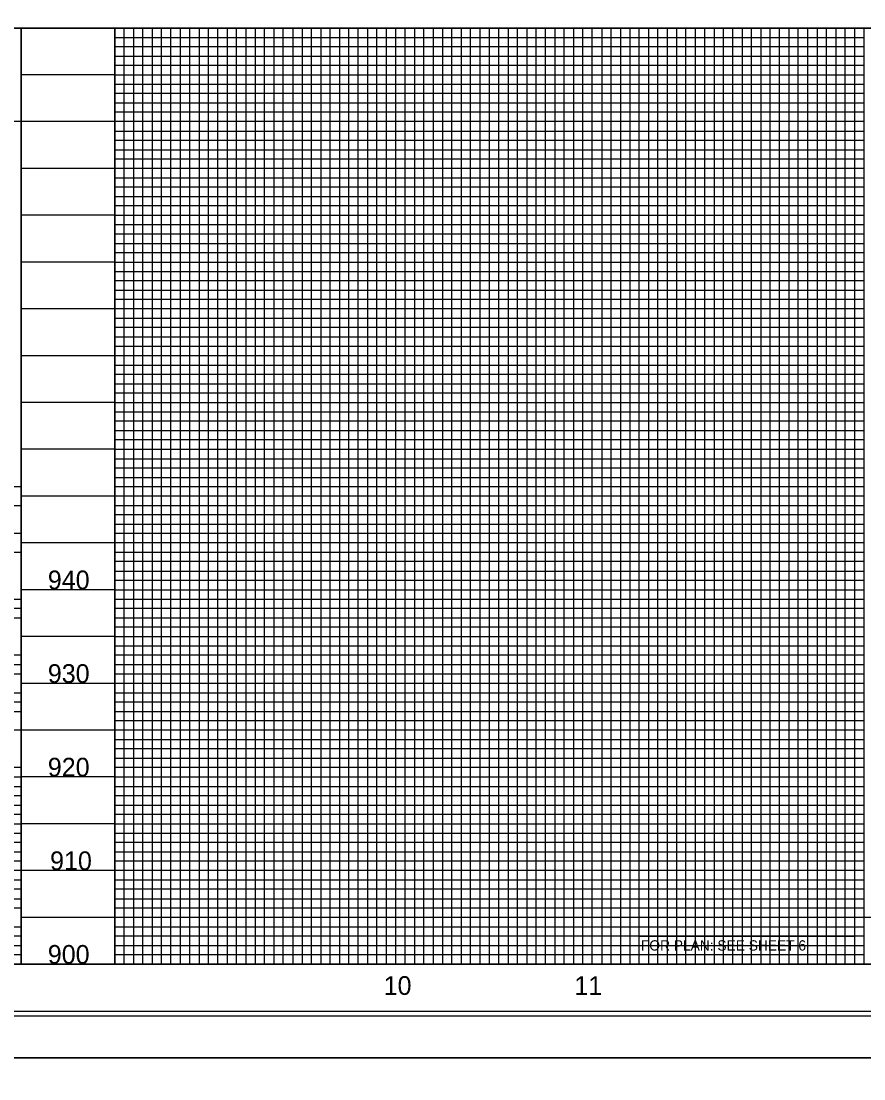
# Model space of a CAD drawing. Extents: x 1967929 to 1975641, y 546296 to 568534.
# Drawn here: x 1970531 to 1970981, y 565223 to 565788 of the extents above; entities that cross this region are included whole.
import ezdxf

# ---------------------------------------------------------------- set-up
doc = ezdxf.new("R2010")
doc.units = 0
for name, color, linetype in [('Exist Vertical Profile Horizontal Axis Label Major', 7, 'Continuous'), ('Exist Vertical Profile Vertical Axis Label', 7, 'Continuous'), ('Prop Grid Mask', 7, 'Continuous'), ('Scratch_Level_3', 7, 'Continuous'), ('Sheet Cutting Line CELL', 7, 'Continuous'), ('Sheet Plot Border Inside CELL', 7, 'Continuous'), ('Sheet Plot Border Outside CELL', 7, 'Continuous'), ('Sheet Profile CELL', 7, 'Continuous'), ('Sheet Profile Grid Major CELL', 7, 'Continuous'), ('Sheet Profile Grid Middle CELL', 7, 'Continuous'), ('Sheet Profile Grid Minor CELL', 7, 'Continuous')]:
    doc.layers.add(name, color=color, linetype=linetype)

msp = doc.modelspace()

# ---------------------------------------------------------------- linework, layer by layer
at = {"layer": 'Prop Grid Mask'}
msp.add_lwpolyline([(1970861.53, 565298.9), (1970976.41, 565298.9), (1970976.41, 565288.87), (1970861.53, 565288.87)], close=True, dxfattribs=at)
at = {"layer": 'Scratch_Level_3'}
for points in [[(1970081.45, 565783.86), (1970081.45, 565283.86), (1971481.45, 565283.86), (1971481.45, 565783.86)], [(1970081.45, 565783.86), (1970081.45, 565283.86), (1971381.45, 565283.86), (1971381.45, 565783.86)], [(1970081.45, 565783.86), (1970081.45, 565283.86), (1971481.45, 565283.86), (1971481.45, 565783.86)]]:
    msp.add_lwpolyline(points, close=True, dxfattribs=at)
at = {"layer": 'Sheet Cutting Line CELL'}
msp.add_line((1969864.45, 565233.86), (1971548.45, 565233.86), dxfattribs=at)
at = {"layer": 'Sheet Plot Border Inside CELL'}
msp.add_lwpolyline([(1969877.45, 565256.31), (1971543.95, 565256.31), (1971543.95, 566311.41), (1969877.45, 566311.41)], close=True, dxfattribs=at)
at = {"layer": 'Sheet Plot Border Outside CELL'}
for points in [[(1969864.45, 565233.86), (1971548.45, 565233.86), (1971548.45, 566333.86), (1969864.45, 566333.86)], [(1969864.45, 564133.86), (1971548.45, 564133.86), (1971548.45, 565233.86), (1969864.45, 565233.86)]]:
    msp.add_lwpolyline(points, close=True, dxfattribs=at)
at = {"layer": 'Sheet Profile CELL'}
for p, q in [((1971531.45, 565783.86), (1970031.45, 565783.86)), ((1971531.45, 565283.86), (1970031.45, 565283.86))]:
    msp.add_line(p, q, dxfattribs=at)
msp.add_lwpolyline([(1971531.45, 566308.86), (1970031.45, 566308.86), (1970031.45, 565258.86), (1971531.45, 565258.86)], close=True, dxfattribs=at)
at = {"layer": 'Sheet Profile Grid Major CELL'}
for points in [[(1970531.45, 565733.86), (1970031.45, 565733.86), (1970031.45, 565783.86), (1971531.45, 565783.86)], [(1970481.45, 565783.86), (1970481.45, 565283.86), (1970531.45, 565283.86), (1970531.45, 565783.86)], [(1970531.45, 565783.86), (1970531.45, 565283.86), (1970581.45, 565283.86), (1970581.45, 565783.86)], [(1970581.45, 565783.86), (1970581.45, 565283.86), (1970631.45, 565283.86), (1970631.45, 565783.86)], [(1970681.45, 565783.86), (1970681.45, 565283.86), (1970731.45, 565283.86), (1970731.45, 565783.86)], [(1970781.45, 565783.86), (1970781.45, 565283.86), (1970831.45, 565283.86), (1970831.45, 565783.86)], [(1970881.45, 565783.86), (1970881.45, 565283.86), (1970931.45, 565283.86), (1970931.45, 565783.86)], [(1970981.45, 565288.86), (1970981.45, 565283.86), (1971031.45, 565283.86), (1971031.45, 565783.86)], [(1970981.45, 565783.86), (1970981.45, 565283.86), (1971031.45, 565283.86), (1971031.45, 565783.86)], [(1970581.45, 565733.86), (1970531.45, 565733.86)], [(1970981.45, 565733.86), (1970581.45, 565733.86)], [(1970581.45, 565683.86), (1970531.45, 565683.86)], [(1970581.45, 565683.86), (1970981.45, 565683.86)], [(1970581.45, 565633.86), (1970531.45, 565633.86)], [(1970981.45, 565633.86), (1970581.45, 565633.86)], [(1970581.45, 565583.86), (1970531.45, 565583.86)], [(1970581.45, 565583.86), (1970981.45, 565583.86)], [(1970581.45, 565533.86), (1970531.45, 565533.86)], [(1970981.45, 565533.86), (1970581.45, 565533.86)], [(1970581.45, 565483.86), (1970531.45, 565483.86)], [(1970581.45, 565483.86), (1970981.45, 565483.86)], [(1970581.45, 565433.86), (1970531.45, 565433.86)], [(1970981.45, 565433.86), (1970581.45, 565433.86)], [(1970531.45, 565333.86), (1970031.45, 565333.86), (1970031.45, 565383.86), (1970531.45, 565383.86)], [(1970581.45, 565383.86), (1970531.45, 565383.86)], [(1970581.45, 565383.86), (1970981.45, 565383.86)], [(1970581.45, 565333.86), (1970531.45, 565333.86)], [(1970981.45, 565333.86), (1970581.45, 565333.86)]]:
    msp.add_lwpolyline(points, dxfattribs=at)
at = {"layer": 'Sheet Profile Grid Middle CELL'}
for p, q in [((1970606.45, 565283.86), (1970606.45, 565783.86)), ((1970956.45, 565783.86), (1970956.45, 565283.86)), ((1970556.45, 565283.86), (1970606.45, 565283.86)), ((1970956.45, 565283.86), (1971006.45, 565283.86))]:
    msp.add_line(p, q, dxfattribs=at)
for points in [[(1970656.45, 565783.86), (1970656.45, 565283.86), (1970706.45, 565283.86), (1970706.45, 565783.86)], [(1970756.45, 565783.86), (1970756.45, 565283.86), (1970806.45, 565283.86), (1970806.45, 565783.86)], [(1970856.45, 565783.86), (1970856.45, 565283.86), (1970906.45, 565283.86), (1970906.45, 565783.86)], [(1970581.45, 565758.86), (1970531.45, 565758.86)], [(1970581.45, 565758.86), (1970981.45, 565758.86)], [(1970581.45, 565708.86), (1970531.45, 565708.86)], [(1970981.45, 565708.86), (1970581.45, 565708.86)], [(1970581.45, 565658.86), (1970531.45, 565658.86)], [(1970581.45, 565658.86), (1970981.45, 565658.86)], [(1970581.45, 565608.86), (1970531.45, 565608.86)], [(1970981.45, 565608.86), (1970581.45, 565608.86)], [(1970581.45, 565558.86), (1970531.45, 565558.86)], [(1970581.45, 565558.86), (1970981.45, 565558.86)], [(1970581.45, 565508.86), (1970531.45, 565508.86)], [(1970981.45, 565508.86), (1970581.45, 565508.86)], [(1970581.45, 565458.86), (1970531.45, 565458.86)], [(1970581.45, 565458.86), (1970981.45, 565458.86)], [(1970531.45, 565408.86), (1970031.45, 565408.86), (1970031.45, 565358.86), (1970531.45, 565358.86)], [(1970581.45, 565408.86), (1970531.45, 565408.86)], [(1970981.45, 565408.86), (1970581.45, 565408.86)], [(1970581.45, 565358.86), (1970531.45, 565358.86)], [(1970581.45, 565358.86), (1970981.45, 565358.86)], [(1970581.45, 565308.86), (1970531.45, 565308.86)], [(1970981.45, 565308.86), (1970581.45, 565308.86)], [(1971031.45, 565308.86), (1970981.45, 565308.86)]]:
    msp.add_lwpolyline(points, dxfattribs=at)
at = {"layer": 'Sheet Profile Grid Minor CELL'}
for p, q in [((1970586.45, 565283.86), (1970586.45, 565783.86)), ((1970976.45, 565783.86), (1970976.45, 565283.86)), ((1970576.45, 565283.86), (1970586.45, 565283.86)), ((1970976.45, 565283.86), (1970986.45, 565283.86))]:
    msp.add_line(p, q, dxfattribs=at)
for points in [[(1970591.45, 565783.86), (1970591.45, 565283.86), (1970596.45, 565283.86), (1970596.45, 565783.86)], [(1970601.45, 565783.86), (1970601.45, 565283.86)], [(1970611.45, 565283.86), (1970611.45, 565783.86)], [(1970616.45, 565783.86), (1970616.45, 565283.86), (1970621.45, 565283.86), (1970621.45, 565783.86)], [(1970626.45, 565783.86), (1970626.45, 565283.86), (1970636.45, 565283.86), (1970636.45, 565783.86)], [(1970641.45, 565783.86), (1970641.45, 565283.86), (1970641.45, 565283.86), (1970646.45, 565283.86), (1970646.45, 565783.86)], [(1970651.45, 565783.86), (1970651.45, 565283.86), (1970661.45, 565283.86), (1970661.45, 565783.86)], [(1970666.45, 565783.86), (1970666.45, 565283.86), (1970671.45, 565283.86), (1970671.45, 565783.86)], [(1970676.45, 565783.86), (1970676.45, 565283.86), (1970686.45, 565283.86), (1970686.45, 565783.86)], [(1970691.45, 565783.86), (1970691.45, 565283.86), (1970696.45, 565283.86), (1970696.45, 565783.86)], [(1970701.45, 565783.86), (1970701.45, 565283.86), (1970711.45, 565283.86), (1970711.45, 565783.86)], [(1970716.45, 565783.86), (1970716.45, 565283.86), (1970721.45, 565283.86), (1970721.45, 565783.86)], [(1970726.45, 565783.86), (1970726.45, 565283.86), (1970736.45, 565283.86), (1970736.45, 565783.86)], [(1970741.45, 565783.86), (1970741.45, 565283.86), (1970746.45, 565283.86), (1970746.45, 565783.86)], [(1970751.45, 565783.86), (1970751.45, 565283.86), (1970761.45, 565283.86), (1970761.45, 565783.86)], [(1970766.45, 565783.86), (1970766.45, 565283.86), (1970771.45, 565283.86), (1970771.45, 565783.86)], [(1970776.45, 565783.86), (1970776.45, 565283.86), (1970786.45, 565283.86), (1970786.45, 565783.86)], [(1970791.45, 565783.86), (1970791.45, 565283.86)], [(1970791.45, 565283.86), (1970796.45, 565283.86), (1970796.45, 565783.86)], [(1970801.45, 565783.86), (1970801.45, 565283.86), (1970811.45, 565283.86), (1970811.45, 565783.86)], [(1970816.45, 565783.86), (1970816.45, 565283.86), (1970821.45, 565283.86), (1970821.45, 565783.86)], [(1970826.45, 565783.86), (1970826.45, 565283.86), (1970836.45, 565283.86), (1970836.45, 565783.86)], [(1970841.45, 565783.86), (1970841.45, 565283.86), (1970846.45, 565283.86), (1970846.45, 565783.86)], [(1970851.45, 565783.86), (1970851.45, 565283.86), (1970861.45, 565283.86), (1970861.45, 565783.86)], [(1970866.45, 565783.86), (1970866.45, 565283.86), (1970871.45, 565283.86), (1970871.45, 565783.86)], [(1970876.45, 565783.86), (1970876.45, 565283.86), (1970886.45, 565283.86), (1970886.45, 565783.86)], [(1970891.45, 565783.86), (1970891.45, 565283.86), (1970896.45, 565283.86), (1970896.45, 565783.86)], [(1970901.45, 565783.86), (1970901.45, 565283.86), (1970911.45, 565283.86), (1970911.45, 565783.86)], [(1970916.45, 565783.86), (1970916.45, 565283.86), (1970921.45, 565283.86), (1970921.45, 565783.86)], [(1970926.45, 565783.86), (1970926.45, 565283.86), (1970936.45, 565283.86), (1970936.45, 565783.86)], [(1970941.45, 565783.86), (1970941.45, 565283.86), (1970946.45, 565283.86), (1970946.45, 565783.86)], [(1970951.45, 565783.86), (1970951.45, 565283.86), (1970961.45, 565283.86), (1970961.45, 565783.86)], [(1970966.45, 565783.86), (1970966.45, 565283.86), (1970971.45, 565283.86), (1970971.45, 565783.86)], [(1970581.45, 565778.86), (1970981.45, 565778.86)], [(1970981.45, 565773.86), (1970581.45, 565773.86)], [(1970581.45, 565768.86), (1970981.45, 565768.86)], [(1970981.45, 565763.86), (1970581.45, 565763.86)], [(1970581.45, 565753.86), (1970981.45, 565753.86)], [(1970981.45, 565748.86), (1970581.45, 565748.86)], [(1970581.45, 565743.86), (1970981.45, 565743.86)], [(1970981.45, 565738.86), (1970581.45, 565738.86)], [(1970581.45, 565728.86), (1970981.45, 565728.86)], [(1970981.45, 565723.86), (1970581.45, 565723.86)], [(1970581.45, 565718.86), (1970981.45, 565718.86)], [(1970981.45, 565713.86), (1970581.45, 565713.86)], [(1970581.45, 565703.86), (1970981.45, 565703.86)], [(1970981.45, 565698.86), (1970581.45, 565698.86)], [(1970581.45, 565693.86), (1970981.45, 565693.86)], [(1970981.45, 565688.86), (1970581.45, 565688.86)], [(1970581.45, 565678.86), (1970981.45, 565678.86)], [(1970981.45, 565673.86), (1970581.45, 565673.86)], [(1970581.45, 565668.86), (1970981.45, 565668.86)], [(1970981.45, 565663.86), (1970581.45, 565663.86)], [(1970581.45, 565653.86), (1970981.45, 565653.86)], [(1970981.45, 565648.86), (1970581.45, 565648.86)], [(1970581.45, 565643.86), (1970981.45, 565643.86)], [(1970981.45, 565638.86), (1970581.45, 565638.86)], [(1970581.45, 565628.86), (1970981.45, 565628.86)], [(1970981.45, 565623.86), (1970581.45, 565623.86)], [(1970581.45, 565618.86), (1970981.45, 565618.86)], [(1970981.45, 565613.86), (1970581.45, 565613.86)], [(1970581.45, 565603.86), (1970981.45, 565603.86)], [(1970981.45, 565598.86), (1970581.45, 565598.86)], [(1970581.45, 565593.86), (1970981.45, 565593.86)], [(1970981.45, 565588.86), (1970581.45, 565588.86)], [(1970581.45, 565578.86), (1970981.45, 565578.86)], [(1970981.45, 565573.86), (1970581.45, 565573.86)], [(1970581.45, 565568.86), (1970981.45, 565568.86)], [(1970981.45, 565563.86), (1970581.45, 565563.86)], [(1970581.45, 565553.86), (1970981.45, 565553.86)], [(1970981.45, 565548.86), (1970581.45, 565548.86)], [(1970581.45, 565543.86), (1970981.45, 565543.86)], [(1970531.45, 565538.86), (1970081.45, 565538.86), (1970081.45, 565528.86), (1970531.45, 565528.86)], [(1970981.45, 565538.86), (1970581.45, 565538.86)], [(1970581.45, 565528.86), (1970981.45, 565528.86)], [(1970981.45, 565523.86), (1970581.45, 565523.86)], [(1970581.45, 565518.86), (1970981.45, 565518.86)], [(1970531.45, 565513.86), (1970081.45, 565513.86), (1970081.45, 565503.86), (1970531.45, 565503.86)], [(1970981.45, 565513.86), (1970581.45, 565513.86)], [(1970581.45, 565503.86), (1970981.45, 565503.86)], [(1970981.45, 565498.86), (1970581.45, 565498.86)], [(1970581.45, 565493.86), (1970981.45, 565493.86)], [(1970981.45, 565488.86), (1970581.45, 565488.86)], [(1970081.45, 565478.86), (1970531.45, 565478.86)], [(1970581.45, 565478.86), (1970981.45, 565478.86)], [(1970531.45, 565473.86), (1970081.45, 565473.86), (1970081.45, 565468.86), (1970531.45, 565468.86)], [(1970981.45, 565473.86), (1970581.45, 565473.86)], [(1970581.45, 565468.86), (1970981.45, 565468.86)], [(1970981.45, 565463.86), (1970581.45, 565463.86)], [(1970581.45, 565453.86), (1970981.45, 565453.86)], [(1970531.45, 565448.86), (1970081.45, 565448.86), (1970081.45, 565443.86), (1970531.45, 565443.86)], [(1970981.45, 565448.86), (1970581.45, 565448.86)], [(1970581.45, 565443.86), (1970981.45, 565443.86)], [(1970531.45, 565438.86), (1970081.45, 565438.86), (1970081.45, 565428.86), (1970531.45, 565428.86)], [(1970981.45, 565438.86), (1970581.45, 565438.86)], [(1970531.45, 565423.86), (1970081.45, 565423.86), (1970081.45, 565418.86), (1970531.45, 565418.86)], [(1970581.45, 565428.86), (1970981.45, 565428.86)], [(1970981.45, 565423.86), (1970581.45, 565423.86)], [(1970581.45, 565418.86), (1970981.45, 565418.86)], [(1970981.45, 565413.86), (1970581.45, 565413.86)], [(1970581.45, 565403.86), (1970981.45, 565403.86)], [(1970981.45, 565398.86), (1970581.45, 565398.86)], [(1970581.45, 565393.86), (1970981.45, 565393.86)], [(1970531.45, 565388.86), (1970081.45, 565388.86), (1970081.45, 565378.86), (1970531.45, 565378.86)], [(1970981.45, 565388.86), (1970581.45, 565388.86)], [(1970581.45, 565378.86), (1970981.45, 565378.86)], [(1970531.45, 565373.86), (1970081.45, 565373.86), (1970081.45, 565368.86), (1970531.45, 565368.86)], [(1970981.45, 565373.86), (1970581.45, 565373.86)], [(1970581.45, 565368.86), (1970981.45, 565368.86)], [(1970531.45, 565363.86), (1970081.45, 565363.86), (1970081.45, 565353.86), (1970531.45, 565353.86)], [(1970981.45, 565363.86), (1970581.45, 565363.86)], [(1970581.45, 565353.86), (1970981.45, 565353.86)], [(1970531.45, 565348.86), (1970081.45, 565348.86), (1970081.45, 565343.86), (1970531.45, 565343.86)], [(1970981.45, 565348.86), (1970581.45, 565348.86)], [(1970581.45, 565343.86), (1970981.45, 565343.86)], [(1970531.45, 565338.86), (1970081.45, 565338.86), (1970081.45, 565328.86), (1970531.45, 565328.86)], [(1970981.45, 565338.86), (1970581.45, 565338.86)], [(1970581.45, 565328.86), (1970981.45, 565328.86)], [(1970531.45, 565323.86), (1970081.45, 565323.86), (1970081.45, 565318.86), (1970531.45, 565318.86)], [(1970981.45, 565323.86), (1970581.45, 565323.86)], [(1970581.45, 565318.86), (1970981.45, 565318.86)], [(1970531.45, 565313.86), (1970081.45, 565313.86), (1970081.45, 565303.86), (1970531.45, 565303.86)], [(1970981.45, 565313.86), (1970581.45, 565313.86)], [(1970581.45, 565303.86), (1970981.45, 565303.86)], [(1970531.45, 565298.86), (1970081.45, 565298.86), (1970081.45, 565293.86), (1970531.45, 565293.86)], [(1970981.45, 565298.86), (1970581.45, 565298.86)], [(1970581.45, 565293.86), (1970981.45, 565293.86)], [(1970531.45, 565288.86), (1970081.45, 565288.86)], [(1970981.45, 565288.86), (1970581.45, 565288.86)]]:
    msp.add_lwpolyline(points, dxfattribs=at)

# ---------------------------------------------------------------- texts
at = {"layer": 'Exist Vertical Profile Horizontal Axis Label Major'}
for s, p in [('10', (1970725.03, 565267.47)), ('11', (1970826.87, 565267.47))]:
    msp.add_text(s, height=10, dxfattribs=at).set_placement(p)
at = {"layer": 'Exist Vertical Profile Vertical Axis Label'}
for s, p in [('940', (1970545.69, 565484.11)), ('930', (1970545.69, 565434.11)), ('920', (1970545.69, 565384.11)), ('910', (1970546.89, 565334.11)), ('900', (1970545.69, 565284.11))]:
    msp.add_text(s, height=10, dxfattribs=at).set_placement(p)
at = {"layer": 'Prop Grid Mask'}
msp.add_text('FOR PLAN: SEE SHEET 6', height=5.4932, dxfattribs=at).set_placement((1970862.42, 565291.16))

doc.saveas('drawing.dxf')
